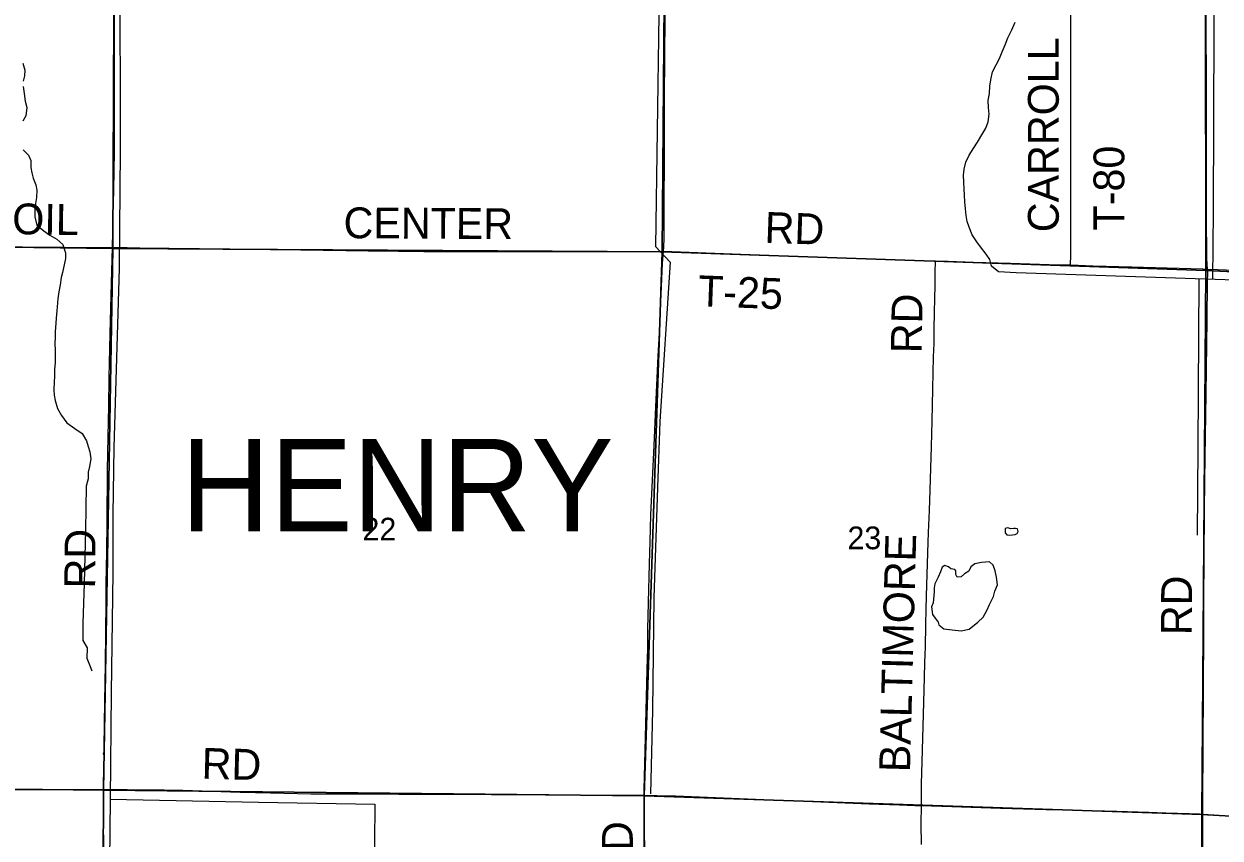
# Model space of a CAD drawing. Extents: x 1443599 to 1910620, y 1028088 to 1361369.
# Drawn here: x 1635252 to 1646892, y 1166571 to 1174491 of the extents above; entities that cross this region are included whole.
import ezdxf

# ---------------------------------------------------------------- set-up
doc = ezdxf.new("R2010")
doc.units = 0
for name, color, linetype in [('GM_X_County_Road', 7, 'Continuous'), ('GM_X_County_Road_Text', 7, 'Continuous'), ('GM_X_Minor_Lake', 7, 'Continuous'), ('GM_X_Minor_River', 7, 'Continuous'), ('GM_X_Section', 7, 'Continuous'), ('GM_X_Section_Text', 7, 'Continuous'), ('GM_X_Township_Road', 7, 'Continuous'), ('GM_X_Township_Road_Text', 7, 'Continuous'), ('GM_X_Township_Text', 7, 'Continuous')]:
    doc.layers.add(name, color=color, linetype=linetype)

msp = doc.modelspace()

# ---------------------------------------------------------------- linework, layer by layer
at = {"layer": 'GM_X_County_Road'}
for points in [[(1636113, 1172317), (1636121, 1172627), (1636128, 1172873), (1636135, 1173250), (1636134, 1173415), (1636135, 1173611), (1636134, 1173890), (1636134, 1174284), (1636136, 1174941), (1636136, 1174946)], [(1636028, 1167044), (1636028, 1167097), (1636032, 1167376), (1636027, 1167393), (1636032, 1167409), (1636033, 1167458), (1636040, 1167901), (1636045, 1168262), (1636053, 1168870), (1636054, 1169034), (1636058, 1169362), (1636063, 1169641), (1636067, 1170149), (1636071, 1170478), (1636077, 1170773), (1636082, 1171052), (1636091, 1171478), (1636104, 1171971), (1636113, 1172315), (1636113, 1172317)], [(1636016, 1164410), (1636019, 1164587), (1636023, 1164833), (1636026, 1165128), (1636031, 1165473), (1636032, 1165916), (1636027, 1166835), (1636028, 1167044)]]:
    msp.add_lwpolyline(points, dxfattribs=at)
at = {"layer": 'GM_X_Minor_Lake'}
for p, q in [((1644886, 1169583), (1644856, 1169579)), ((1644108, 1168966), (1644100, 1168860))]:
    msp.add_line(p, q, dxfattribs=at)
for points in [[(1644856, 1169579), (1644828, 1169588), (1644802, 1169582), (1644800, 1169560), (1644799, 1169540), (1644817, 1169522), (1644839, 1169519), (1644871, 1169521), (1644897, 1169523), (1644918, 1169534), (1644926, 1169554), (1644922, 1169578), (1644902, 1169583), (1644886, 1169583)], [(1644100, 1168860), (1644084, 1168820), (1644093, 1168746), (1644120, 1168710), (1644150, 1168673), (1644155, 1168647), (1644203, 1168608), (1644285, 1168597), (1644373, 1168588), (1644451, 1168603), (1644536, 1168670), (1644585, 1168719), (1644624, 1168791), (1644647, 1168844), (1644686, 1168920), (1644701, 1168972), (1644726, 1169036), (1644717, 1169108), (1644704, 1169172), (1644685, 1169227), (1644649, 1169259), (1644571, 1169253), (1644505, 1169239), (1644468, 1169210), (1644447, 1169166), (1644405, 1169143), (1644371, 1169113), (1644332, 1169110), (1644319, 1169136), (1644319, 1169170), (1644310, 1169184), (1644272, 1169189), (1644248, 1169209), (1644214, 1169222), (1644186, 1169206), (1644171, 1169160), (1644150, 1169110), (1644136, 1169082), (1644115, 1169043), (1644109, 1169005), (1644108, 1168966)]]:
    msp.add_lwpolyline(points, dxfattribs=at)
at = {"layer": 'GM_X_Minor_River'}
for points in [[(1646653, 1186044), (1646678, 1184793), (1646676, 1183097), (1646676, 1182758), (1646810, 1182630), (1646806, 1181917), (1646810, 1180208), (1646814, 1179216), (1646814, 1177974), (1646814, 1176820), (1646830, 1174453), (1646826, 1172665), (1646818, 1172005)], [(1636197, 1177676), (1636191, 1176225), (1636185, 1175109), (1636189, 1173255), (1636179, 1172111), (1636128, 1170370), (1636116, 1169719), (1636116, 1169152), (1636102, 1167988), (1636090, 1166949), (1636079, 1165739), (1636077, 1164592), (1636063, 1163564), (1636056, 1161932), (1636060, 1160598), (1636048, 1158268)], [(1641445, 1176138), (1641431, 1174584), (1641397, 1172327), (1641541, 1172174), (1641441, 1170623), (1641417, 1169983), (1641381, 1168908), (1641370, 1167811), (1641350, 1167002)], [(1644909, 1172069), (1644735, 1172081), (1644666, 1172134), (1644650, 1172200), (1644614, 1172252), (1644562, 1172322), (1644524, 1172372), (1644478, 1172441), (1644450, 1172513), (1644432, 1172569), (1644420, 1172627), (1644414, 1172693), (1644408, 1172762), (1644404, 1172826), (1644402, 1172886), (1644398, 1172952), (1644394, 1173019), (1644400, 1173079), (1644418, 1173147), (1644450, 1173215), (1644496, 1173285), (1644530, 1173340), (1644582, 1173428), (1644612, 1173478), (1644634, 1173540), (1644644, 1173614), (1644638, 1173679), (1644636, 1173747), (1644648, 1173815), (1644652, 1173887), (1644660, 1173947), (1644678, 1174024), (1644712, 1174094), (1644744, 1174156), (1644771, 1174218), (1644801, 1174289), (1644825, 1174357), (1644865, 1174433), (1644897, 1174507)], [(1635243, 1174110), (1635261, 1174042), (1635259, 1173986), (1635245, 1173935)], [(1635245, 1173881), (1635253, 1173813), (1635263, 1173739), (1635279, 1173677), (1635271, 1173598), (1635241, 1173544)], [(1635245, 1173267), (1635297, 1173213), (1635319, 1173163), (1635321, 1173093), (1635329, 1173042), (1635341, 1172990), (1635369, 1172926), (1635377, 1172874), (1635373, 1172804), (1635365, 1172743), (1635357, 1172687), (1635359, 1172615), (1635379, 1172535), (1635445, 1172479), (1635505, 1172436), (1635574, 1172396), (1635632, 1172344), (1635658, 1172264), (1635656, 1172210), (1635644, 1172149), (1635626, 1172073), (1635616, 1172023), (1635606, 1171953), (1635592, 1171885), (1635582, 1171816), (1635573, 1171700), (1635567, 1171630), (1635563, 1171580), (1635557, 1171497), (1635555, 1171445), (1635553, 1171383), (1635557, 1171313), (1635555, 1171255), (1635555, 1171198), (1635551, 1171128), (1635551, 1171062), (1635547, 1171010), (1635543, 1170933), (1635547, 1170881), (1635555, 1170827), (1635579, 1170751)], [(1649695, 1171888), (1647423, 1171985), (1644909, 1172069)], [(1646686, 1172009), (1646676, 1170371), (1646669, 1169519)], [(1635579, 1170751), (1635619, 1170681), (1635670, 1170610), (1635746, 1170556), (1635820, 1170506), (1635862, 1170436), (1635878, 1170380), (1635894, 1170329), (1635902, 1170261), (1635890, 1170185), (1635878, 1170131), (1635878, 1170067), (1635858, 1169994)], [(1635858, 1169994), (1635852, 1169565), (1635840, 1169051), (1635826, 1168660), (1635826, 1168494), (1635868, 1168423), (1635866, 1168321), (1635896, 1168241), (1635914, 1168199)], [(1636090, 1166949), (1637536, 1166920), (1638666, 1166900), (1638656, 1165771), (1638653, 1164497), (1638705, 1164453), (1638703, 1164013), (1638707, 1162276), (1638700, 1160098), (1638694, 1158759)]]:
    msp.add_lwpolyline(points, dxfattribs=at)
at = {"layer": 'GM_X_Section'}
for points in [[(1636139, 1177592), (1636116, 1172306), (1630731, 1172373), (1630778, 1177642)], [(1641506, 1177542), (1641463, 1172273), (1636116, 1172306), (1636139, 1177592)], [(1646746, 1177387), (1646752, 1172091), (1641463, 1172273), (1641506, 1177542)], [(1652028, 1177118), (1652028, 1177094), (1652051, 1171840), (1646752, 1172091), (1646746, 1177387)], [(1636116, 1172306), (1636027, 1167036), (1630682, 1167094), (1630731, 1172373)], [(1641463, 1172273), (1641288, 1166981), (1636027, 1167036), (1636116, 1172306)], [(1646752, 1172091), (1646713, 1166800), (1641288, 1166981), (1641463, 1172273)], [(1652051, 1171840), (1652036, 1166584), (1649602, 1166636), (1646713, 1166800), (1646752, 1172091)], [(1636027, 1167036), (1636004, 1161791), (1630677, 1161827), (1630682, 1167094)], [(1641288, 1166981), (1641296, 1161695), (1636004, 1161791), (1636027, 1167036)], [(1646713, 1166800), (1646722, 1161506), (1641296, 1161695), (1641288, 1166981)], [(1652036, 1166584), (1652031, 1166558), (1652006, 1161277), (1648100, 1161492), (1646722, 1161506), (1646713, 1166800), (1649602, 1166636)]]:
    msp.add_lwpolyline(points, close=True, dxfattribs=at)
at = {"layer": 'GM_X_Township_Road'}
for points in [[(1645435, 1172146), (1645436, 1172165), (1645440, 1172226), (1645441, 1172275), (1645440, 1172783), (1645440, 1173324), (1645440, 1173930), (1645438, 1174307), (1645440, 1174716), (1645438, 1175028), (1645437, 1175273), (1645435, 1175470), (1645434, 1175798), (1645433, 1175978), (1645433, 1176257), (1645432, 1176666), (1645432, 1177092), (1645433, 1177387), (1645433, 1177425)], [(1646769, 1172106), (1646762, 1172207), (1646762, 1172305), (1646761, 1172535), (1646759, 1173454), (1646758, 1174045), (1646757, 1174340), (1646756, 1174767), (1646755, 1175194), (1646751, 1175686), (1646748, 1176343), (1646745, 1176605), (1646744, 1176917), (1646741, 1177278), (1646741, 1177401)], [(1641475, 1172278), (1641478, 1172323), (1641481, 1172405), (1641482, 1172569), (1641482, 1172815), (1641486, 1173110), (1641487, 1173701), (1641488, 1174243), (1641492, 1174489), (1641492, 1174965), (1641493, 1175211), (1641495, 1175474), (1641494, 1176081), (1641491, 1176459), (1641491, 1176869)], [(1630736, 1172377), (1630743, 1172377), (1630940, 1172373), (1631399, 1172370), (1631661, 1172367), (1631842, 1172365), (1632104, 1172362), (1632449, 1172357), (1632613, 1172355), (1632925, 1172352), (1633253, 1172348), (1633844, 1172340), (1634057, 1172339), (1634533, 1172332), (1634845, 1172328), (1635238, 1172324), (1635632, 1172319), (1635829, 1172317), (1636108, 1172317), (1636113, 1172317)], [(1636113, 1172317), (1636256, 1172316), (1636502, 1172311), (1636666, 1172311), (1637257, 1172302), (1637650, 1172297), (1637946, 1172294), (1638602, 1172284), (1638898, 1172282), (1639144, 1172278), (1639636, 1172276), (1640013, 1172277), (1640522, 1172277), (1640850, 1172276), (1641113, 1172277), (1641310, 1172277), (1641475, 1172278)], [(1641287, 1166987), (1641288, 1167042), (1641299, 1167419), (1641308, 1167813), (1641317, 1168207), (1641322, 1168420), (1641324, 1168600), (1641331, 1168863), (1641341, 1169240), (1641345, 1169454), (1641353, 1169716), (1641384, 1170389), (1641402, 1170766), (1641425, 1171258), (1641436, 1171487), (1641466, 1172159), (1641471, 1172241), (1641475, 1172278)], [(1641475, 1172278), (1641507, 1172278), (1641556, 1172277), (1642228, 1172251), (1642687, 1172236), (1642966, 1172225), (1643737, 1172196), (1643966, 1172191), (1644098, 1172186), (1644122, 1172186)], [(1643986, 1166887), (1643986, 1166919), (1643987, 1166978), (1643987, 1167099), (1643994, 1167313), (1644000, 1167543), (1644005, 1167773), (1644015, 1168134), (1644020, 1168279), (1644023, 1168355), (1644025, 1168430), (1644029, 1168642), (1644033, 1168806), (1644039, 1169036), (1644051, 1169446), (1644055, 1169544), (1644065, 1169758), (1644072, 1169955), (1644078, 1170168), (1644084, 1170381), (1644090, 1170628), (1644097, 1170940), (1644104, 1171252), (1644108, 1171383), (1644111, 1171531), (1644113, 1171678), (1644115, 1171826), (1644118, 1171941), (1644119, 1171990), (1644120, 1172072), (1644120, 1172104), (1644121, 1172152), (1644122, 1172186)], [(1644122, 1172186), (1644245, 1172183), (1644491, 1172175), (1644852, 1172164), (1645229, 1172152), (1645435, 1172146)], [(1645435, 1172146), (1645656, 1172139), (1646033, 1172127), (1646377, 1172118), (1646723, 1172109), (1646769, 1172106)], [(1646724, 1166804), (1646728, 1167595), (1646729, 1167891), (1646730, 1168137), (1646733, 1168465), (1646735, 1168876), (1646736, 1169302), (1646740, 1169745), (1646744, 1170057), (1646750, 1170484), (1646755, 1170894), (1646766, 1171616), (1646769, 1171977), (1646771, 1172074), (1646769, 1172106)], [(1646769, 1172106), (1646869, 1172101), (1647033, 1172096), (1647804, 1172071), (1648017, 1172065), (1648280, 1172057), (1649248, 1172025), (1649706, 1172005), (1650034, 1171986), (1650690, 1171951), (1651008, 1171934)], [(1630686, 1167095), (1630824, 1167093), (1631333, 1167083), (1631973, 1167071), (1632137, 1167068), (1632285, 1167066), (1632580, 1167061), (1633073, 1167054), (1633532, 1167049), (1633942, 1167048), (1634730, 1167045), (1634944, 1167044), (1635239, 1167044), (1635617, 1167043), (1635978, 1167043), (1636028, 1167044)], [(1636028, 1167044), (1636126, 1167046), (1636257, 1167045), (1636618, 1167039), (1636798, 1167037), (1637356, 1167018), (1637652, 1167010), (1638045, 1167003), (1638374, 1167000), (1638620, 1167001), (1638899, 1166997), (1639802, 1166994), (1640327, 1166992), (1641066, 1166988), (1641287, 1166987)], [(1641287, 1166987), (1641410, 1166986), (1641591, 1166981), (1642214, 1166956), (1642608, 1166941), (1643165, 1166917), (1643477, 1166905), (1643772, 1166895), (1643920, 1166889), (1643985, 1166887), (1643986, 1166887)], [(1641305, 1164339), (1641302, 1164809), (1641302, 1164990), (1641301, 1165367), (1641300, 1165646), (1641298, 1165860), (1641296, 1166106), (1641294, 1166401), (1641292, 1166697), (1641287, 1166959), (1641287, 1166987)], [(1643985, 1166508), (1643983, 1166705), (1643986, 1166887)], [(1643986, 1166887), (1644084, 1166885), (1644280, 1166877), (1644756, 1166863), (1645199, 1166850), (1645527, 1166843), (1645888, 1166832), (1646200, 1166823), (1646364, 1166817), (1646594, 1166811), (1646692, 1166806), (1646724, 1166804)], [(1646719, 1164167), (1646719, 1164193), (1646719, 1164444), (1646719, 1164658), (1646721, 1165856), (1646721, 1166135), (1646720, 1166381), (1646723, 1166562), (1646724, 1166804)], [(1646724, 1166804), (1646938, 1166792), (1647692, 1166749), (1647954, 1166735), (1648233, 1166721), (1648577, 1166703), (1648741, 1166694), (1648954, 1166680), (1649298, 1166661), (1649708, 1166644), (1650036, 1166629), (1650347, 1166615), (1650774, 1166601), (1651036, 1166589), (1651151, 1166587), (1651217, 1166587), (1651267, 1166587)]]:
    msp.add_lwpolyline(points, dxfattribs=at)

# ---------------------------------------------------------------- texts
at = {"layer": 'GM_X_County_Road_Text'}
msp.add_text('RD', height=300, rotation=89.5063, dxfattribs=at).set_placement((1635945, 1168998))
at = {"layer": 'GM_X_Section_Text'}
for s, p in [('22', (1638547, 1169466)), ('23', (1643266, 1169381))]:
    msp.add_text(s, height=221, rotation=0, dxfattribs=at).set_placement(p)
at = {"layer": 'GM_X_Township_Road_Text'}
for s, rotation, p in [('CARROLL', 90, (1645322, 1172465)), ('T-80', 90, (1645960, 1172482)), ('OIL', 359.1863, (1635137, 1172446)), ('CENTER', 359.6576, (1638362, 1172407)), ('RD', 358.0243, (1642456, 1172363)), ('T-25', 357.8788, (1641808, 1171746)), ('RD', 89.0251, (1643988, 1171286)), ('BALTIMORE', 88.4803, (1643874, 1167209)), ('RD', 89.5053, (1646615, 1168544)), ('RD', 358.5383, (1636979, 1167149)), ('RD', 90.4898, (1641181, 1166157))]:
    msp.add_text(s, height=300, rotation=rotation, dxfattribs=at).set_placement(p)
at = {"layer": 'GM_X_Township_Text'}
msp.add_text('HENRY', height=900, rotation=0, dxfattribs=at).set_placement((1636778, 1169554))

doc.saveas('drawing.dxf')
